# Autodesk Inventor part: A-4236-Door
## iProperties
Author: Administrator
Shininess: 20.0
PropertySet Name: _Private Model Information
Length Units: 11272
Angle Units: 11286
Time Units: 11279
Mass Units: 11290
Length Display Precision: 3
Angle Display Precision: 2
Compacted: True
Created: 2001-02
Part Number: A-4236-Door
Document SubType Name: Sheet Metal
Designer: Administrator
Control State: 0
Master: False
Checked Out: False
PropertySet Name: Design Tracking Control
Density: 0.0
Volumn: 0.0
Area: 0.0
PropertySet Name: Model Information
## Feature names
1. Extrusion1
2. Extrusion2
3. Fillet1
4. Fillet2
5. Shell1
6. Extrusion3
7. Extrusion4
8. Extrusion5
9. Gasket [Extrusion]
10. PrintPocket1 [Extrusion]
11. PrintPocket2 [Extrusion]
12. PrintPocket3 [Extrusion]
13. Fillet5
14. Fillet7
15. CenterBrace [Extrusion]
16. Extrusion11
17. Extrusion12
18. Fillet4
19. Extrusion13
20. Cut3
